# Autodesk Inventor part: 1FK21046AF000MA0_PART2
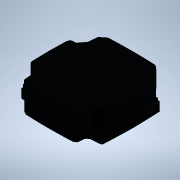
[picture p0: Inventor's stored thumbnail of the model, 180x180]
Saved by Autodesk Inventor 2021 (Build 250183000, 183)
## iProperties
Created: 2025-04
Part Number: 1FK21046AF000MA0_PART2
Material: Generic
Catalog Web Link: www.3dfindit.com
Description: -Servo synchronous motor
Document SubType Name: Modeling
Designer: psAdmin
Mass: 135.825 g
Surface Area: 188.795 cm^2
Volume: 135.825 cm^3
Density: 1 g/cm^3
Appearance: PSOLRGB-38-46-56
Category: PARTsolutions
Title: 1FK21046AF000MA0_PART2
Author: Cadenas PARTsolutions
Comments: Servo synchronous motor
Sending System: PARTsolutions
Preprocessor: ST-DEVELOPER v19.3
PSOL_IDENT_0: {$CADENAS_DATA/23d-libs/siemens_ag/_cat_/1c/1f/1fk21046af000ma0.prj},213 {VTYP=3D},{NB=1FK21046AF000
PSOL_IDENT_1: MA0_PART2},{LINA=1FK21046AF000MA0_PART2},{NN=1FK21046AF000MA0_PART2},{NOPRJ=TRUE},{DATE=19.08.2025 1
PSOL_IDENT_2: 4:00:28},{GEOMDATE=30.07.2025 02:02:08},{VERSION=},{LINEID=10},{WBVAR=},{WBNUMERIC=}  {NB=1FK21046AF
PSOL_IDENT_3: 000MA0_PART2},{LINA=1FK21046AF000MA0_PART2},{KT=DUMMY},{PREVIEW=../../../_pool_/cb/72/p_d211_xx_0043
PSOL_IDENT_4: 4j.png},{DESCSHORT=SIMOTICS S-1FK2 HD, SINAMICS S210 3AC 400V-480V, 3.2 Nm, 3000 rpm},{DESCLONG=SIMO
PSOL_IDENT_5: TICS S-1FK2 HD servo motor M0=3.2 Nm; PN = 1 kW at nN=3000 rpm (380-480 V); PN = 0.5 kW at nN=1500 r
PSOL_IDENT_6: pm (200-240 V); degree of protection IP64; cylindrical shaft D19x40mm; absolute encoder 22-bit + 12-
PSOL_IDENT_7: bit multiturn (encoder AM22DQC); with OCC interface; plug size M17, rotatable; SIMOTICS S-1FK2 servo
PSOL_IDENT_8: motorfor a wide range of uses in industrial environments. SIMOTICS S‑1FK2 servomotors are compact sy
PSOL_IDENT_9: nchronous motors with a high dynamic performance that set themselves apart as a result of their high
PSOL_IDENT_10: power density, degree of protection and overload capability. The motors are available in two varian
PSOL_IDENT_11: ts: as High Dynamic variant (highest dynamic performance as a result of the low intrinsic moment of
PSOL_IDENT_12: inertia for applications demanding a high dynamic performance with low moved masses) - and as Compac
PSOL_IDENT_13: t variant (precise and stable closed-loop control for medium up to large moved masses as a result of
PSOL_IDENT_14: a medium intrinsic moment of inertia). SIMOTICSS‑1FK2 servomotors fully exploit their strengths in
PSOL_IDENT_15: a system with the SINAMICSS210 frequency converter and simple connection using the one cable connect
PSOL_IDENT_16: ion (OCC). Advantages include the short control and positioning times, fast and precise correction o
PSOL_IDENT_17: f disturbing quantities as well as stable control with a high dynamic performance. The servo motors
PSOL_IDENT_18: can be configured to address a wide range of requirements. For example with and without holding brak
PSOL_IDENT_19: e, IP64 or IP65 degree of protection, singleturn or multiturn absolute encoders - to name just a few
PSOL_IDENT_20: . Further, the servomotors are available in different shaft heights extending from 20 to 100. A shaf
PSOL_IDENT_21: t sealing ring is available to achieve an IP65 degree of protection and for subsequent mounting at t
PSOL_IDENT_22: he motor or as spare part. SIMOTICS - the optimum motor for each and every motion control applicatio
PSOL_IDENT_23: n.},{INTNO=195125049666},{SUPPLIERALTNO=1FK2104-6AF00-0MA0},{MANUID=1FK21046AF000MA0},{MANUNAME=Siem
PSOL_IDENT_24: ens},{MANUTYPEDESC=Synchronous motor 1FK2-HD 3.2 NM},{AAU732=SIMOTICS},{AAO057=S-1FK2},{AAU734=SIMOT
PSOL_IDENT_25: ICS S-1FK2 HD servo motor M0=3.2 Nm; PN = 1 kW at nN=3000 rpm (380-480 V); PN = 0.5 kW at nN=1500 rp
PSOL_IDENT_26: m (200-240 V); degree of protection IP64; cylindrical shaft D19x40mm; absolute encoder 22-bit + 12-b
PSOL_IDENT_27: it multiturn (encoder AM22DQC); with OCC interface; plug size M17, rotatable;},{AAW338=Synchronous m
PSOL_IDENT_28: otor 1FK2-HD 3.2 NM},{AAO742=SIMOTICS},{AAO663=4042948694374},{NOCUPEROU=1},{PRICEQUANTITY=1},{QUANT
PSOL_IDENT_29: ITYMIN=1},{QUANTITYINT=1},{CTN=85015220},{COO=DE},{AAO676=1FK2104-6AF00-0MA0},{AAO677=Siemens AG},{O
PSOL_IDENT_30: RDERUNIT=C62},{CONTENTUNIT=C62}
NB: 1FK21046AF000MA0_PART2
NT: Servo synchronous motor
NBSYN: $MANUID._PART2
LINA: 1FK21046AF000MA0_PART2
CATALOG: SIEMENS
PREVIEW: ../../../_pool_/cb/72/p_d211_xx_00434j.png
DESCSHORT: SIMOTICS S-1FK2 HD, SINAMICS S210 3AC 400V-480V, 3.2 Nm, 3000 rpm
DESCLONG: SIMOTICS S-1FK2 HD servo motor M0=3.2 Nm; PN = 1 kW at nN=3000 rpm (380-480 V); PN = 0.5 kW at nN=1500 rpm (200-240 V); degree of protection IP64; cylindrical s
INTNO: 195125049666
SUPPLIERALTNO: 1FK2104-6AF00-0MA0
MANUID: 1FK21046AF000MA0
MANUNAME: Siemens
MANUTYPEDESC: Synchronous motor 1FK2-HD 3.2 NM
AAU732: SIMOTICS
AAO057: S-1FK2
AAU734: SIMOTICS S-1FK2 HD servo motor M0=3.2 Nm; PN = 1 kW at nN=3000 rpm (380-480 V); PN = 0.5 kW at nN=1500 rpm (200-240 V); degree of protection IP64; cylindrical s
AAW338: Synchronous motor 1FK2-HD 3.2 NM
AAO742: SIMOTICS
AAO663: 4042948694374.0
NOCUPEROU: 1
PRICEQUANTITY: 1
QUANTITYMIN: 1
QUANTITYINT: 1
CTN: 85015220
COO: DE
ARTICLENO: 1FK21046AF000MA0_PART2
BOMINFO: 1FK21046AF000MA0_PART2
CREATOR: CADENAS GmbH
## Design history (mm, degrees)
feature "2025_04_17_15_39_11_0299"
body "Solid1"
